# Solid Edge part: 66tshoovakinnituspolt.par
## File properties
Author: KULL
Template: Iso Metric Part.par
Last saved by: KULL
Revision: 7
Application: Solid Edge
Accuracy: 0,990
Face Style: Model Default
Fill Style: Normal
Coef. of Thermal Exp: 0.0
Thermal Conductivity: 0.0
Specific Heat: 0.0
Modulus of Elasticity: 0.0
Poisson's Ratio: 0.0
Yield Stress: 0.0
Ultimate Stress: 0.0
Elongation: 0.0
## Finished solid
Body 1: solid body, 9 faces, 8 edges, 0 vertices.
  Faces by surface: plane 4, cylinder 3, torus 2
  Edges by curve: circle 8
Bounding box of the edges (mm; curved faces can reach further): 62.000 x 7.000 x 7.000, from (-31, 41.5, 53.311) to (31, 48.5, 60.311).
Cylindrical faces by radius (mm): R2.5 x1, R3.5 x2
Toroidal faces (ring radius, tube radius in mm): R2.5 r1 x2
Planar faces by outward normal: +x 2, -x 2
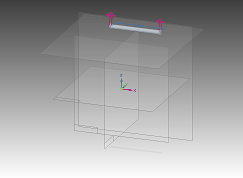
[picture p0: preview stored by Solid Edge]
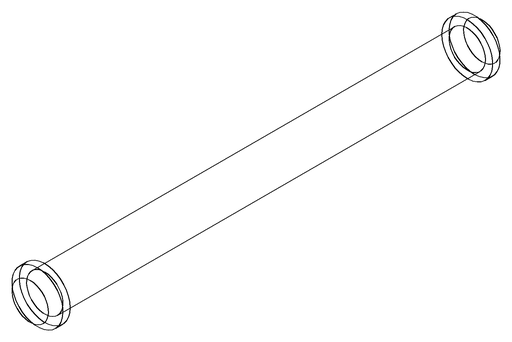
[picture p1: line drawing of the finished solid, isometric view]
